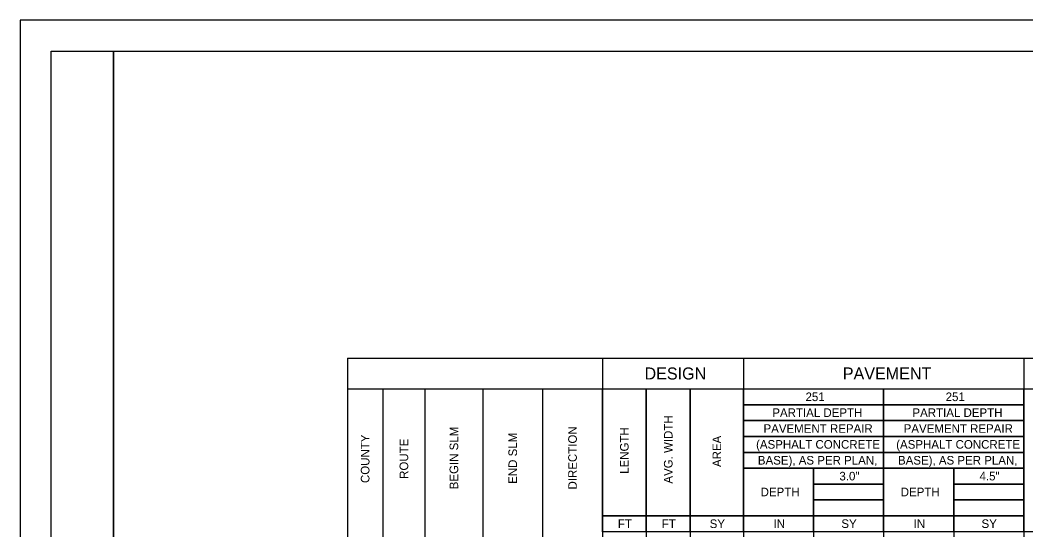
# Model space of a CAD drawing. Extents: x 0 to 34, y 0 to 22.
# Drawn here: x 0 to 16.15, y 13.81 to 22 of the extents above; entities that cross this region are included whole.
import ezdxf

# ---------------------------------------------------------------- set-up
doc = ezdxf.new("R2010")
doc.units = 0
for name, color, linetype in [('SH_Border', 7, 'Continuous'), ('SH_Cut_Line', 7, 'Continuous'), ('SH_Text', 7, 'Continuous')]:
    doc.layers.add(name, color=color, linetype=linetype)

msp = doc.modelspace()

# ---------------------------------------------------------------- linework, layer by layer
at = {"layer": 'SH_Border'}
for points in [[(0.5, 21.5), (1.5, 21.5), (1.5, 0.5), (0.5, 0.5)], [(1.5, 21.5), (33.5, 21.5), (33.5, 0.5), (1.5, 0.5)]]:
    msp.add_lwpolyline(points, close=True, dxfattribs=at)
at = {"layer": 'SH_Cut_Line'}
msp.add_lwpolyline([(0, 0), (34, 0), (34, 22), (0, 22)], close=True, dxfattribs=at)
at = {"layer": 'SH_Text'}
for p, q in [((5.255, 16.568), (27.95, 16.568)), ((5.255, 16.568), (5.255, 5.873)), ((9.35, 16.568), (9.35, 6.638)), ((11.615, 16.568), (11.615, 6.638)), ((16.115, 16.568), (16.115, 5.873)), ((5.255, 16.073), (27.95, 16.073)), ((5.825, 16.073), (5.825, 6.638)), ((6.5, 16.073), (6.5, 6.638)), ((7.43, 16.073), (7.43, 6.638)), ((8.39, 16.073), (8.39, 6.638)), ((10.055, 16.073), (10.055, 6.638)), ((10.76, 16.073), (10.76, 6.638)), ((13.865, 16.073), (13.865, 5.873)), ((11.615, 15.818), (16.115, 15.818)), ((11.615, 14.798), (12.74, 14.798)), ((12.74, 14.798), (12.74, 5.873)), ((13.865, 14.798), (14.99, 14.798)), ((14.99, 14.798), (14.99, 5.873)), ((9.35, 14.033), (16.115, 14.033))]:
    msp.add_line(p, q, dxfattribs=at)
for points in [[(9.35, 16.073), (10.055, 16.073), (10.055, 14.033), (9.35, 14.033)], [(10.055, 16.073), (10.76, 16.073), (10.76, 14.033), (10.055, 14.033)], [(10.76, 16.073), (11.615, 16.073), (11.615, 14.033), (10.76, 14.033)], [(11.615, 16.073), (13.865, 16.073), (13.865, 15.818), (11.615, 15.818)], [(13.865, 16.073), (16.115, 16.073), (16.115, 15.818), (13.865, 15.818)], [(16.115, 16.073), (27.95, 16.073), (27.95, 13.778), (16.115, 13.778)], [(11.615, 15.818), (13.865, 15.818), (13.865, 15.563), (11.615, 15.563)], [(13.865, 15.818), (16.115, 15.818), (16.115, 15.563), (13.865, 15.563)], [(11.615, 15.563), (13.865, 15.563), (13.865, 15.308), (11.615, 15.308)], [(13.865, 15.563), (16.115, 15.563), (16.115, 15.308), (13.865, 15.308)], [(11.615, 15.308), (13.865, 15.308), (13.865, 15.053), (11.615, 15.053)], [(13.865, 15.308), (16.115, 15.308), (16.115, 15.053), (13.865, 15.053)], [(11.615, 15.053), (13.865, 15.053), (13.865, 14.798), (11.615, 14.798)], [(13.865, 15.053), (16.115, 15.053), (16.115, 14.798), (13.865, 14.798)], [(11.615, 14.798), (12.74, 14.798), (12.74, 14.033), (11.615, 14.033)], [(12.74, 14.798), (13.865, 14.798), (13.865, 14.543), (12.74, 14.543)], [(13.865, 14.798), (14.99, 14.798), (14.99, 14.033), (13.865, 14.033)], [(14.99, 14.798), (16.115, 14.798), (16.115, 14.543), (14.99, 14.543)], [(12.74, 14.543), (13.865, 14.543), (13.865, 14.288), (12.74, 14.288)], [(14.99, 14.543), (16.115, 14.543), (16.115, 14.288), (14.99, 14.288)], [(12.74, 14.288), (13.865, 14.288), (13.865, 14.033), (12.74, 14.033)], [(14.99, 14.288), (16.115, 14.288), (16.115, 14.033), (14.99, 14.033)], [(9.35, 14.033), (10.055, 14.033), (10.055, 13.778), (9.35, 13.778)], [(10.055, 14.033), (10.76, 14.033), (10.76, 13.778), (10.055, 13.778)], [(10.76, 14.033), (11.615, 14.033), (11.615, 13.778), (10.76, 13.778)], [(11.615, 14.033), (12.74, 14.033), (12.74, 13.778), (11.615, 13.778)], [(12.74, 14.033), (13.865, 14.033), (13.865, 13.778), (12.74, 13.778)], [(13.865, 14.033), (14.99, 14.033), (14.99, 13.778), (13.865, 13.778)], [(14.99, 14.033), (16.115, 14.033), (16.115, 13.778), (14.99, 13.778)]]:
    msp.add_lwpolyline(points, close=True, dxfattribs=at)

# ---------------------------------------------------------------- texts
for s, height, p in [('DESIGN', 0.1932, (10.026, 16.224)), ('PAVEMENT', 0.1932, (13.21, 16.224)), ('251', 0.138, (12.611, 15.877)), ('251', 0.138, (14.861, 15.877)), ('PARTIAL DEPTH', 0.138, (12.078, 15.622)), ('PARTIAL DEPTH', 0.138, (14.328, 15.622)), ('PAVEMENT REPAIR', 0.138, (11.937, 15.367)), ('PAVEMENT REPAIR', 0.138, (14.187, 15.367)), ('(ASPHALT CONCRETE', 0.138, (11.817, 15.112)), ('(ASPHALT CONCRETE', 0.138, (14.067, 15.112)), ('BASE), AS PER PLAN,', 0.138, (11.846, 14.857)), ('BASE), AS PER PLAN,', 0.138, (14.096, 14.857)), ('3.0"', 0.138, (13.155, 14.602)), ('4.5"', 0.138, (15.405, 14.602)), ('DEPTH', 0.138, (11.89, 14.347)), ('DEPTH', 0.138, (14.14, 14.347)), ('FT', 0.138, (9.598, 13.837)), ('FT', 0.138, (10.303, 13.837)), ('SY', 0.138, (11.072, 13.837)), ('IN', 0.138, (12.098, 13.838)), ('SY', 0.138, (13.187, 13.838)), ('IN', 0.138, (14.348, 13.838)), ('SY', 0.138, (15.437, 13.838))]:
    msp.add_text(s, height=height, dxfattribs=at).set_placement(p)
for s, p in [('AVG. WIDTH', (10.476, 14.551)), ('BEGIN SLM', (7.034, 14.46)), ('END SLM', (7.979, 14.547)), ('DIRECTION', (8.939, 14.456)), ('LENGTH', (9.771, 14.708)), ('COUNTY', (5.609, 14.56)), ('ROUTE', (6.231, 14.627)), ('AREA', (11.256, 14.817))]:
    msp.add_text(s, height=0.138, rotation=90, dxfattribs=at).set_placement(p)

doc.saveas('drawing.dxf')
